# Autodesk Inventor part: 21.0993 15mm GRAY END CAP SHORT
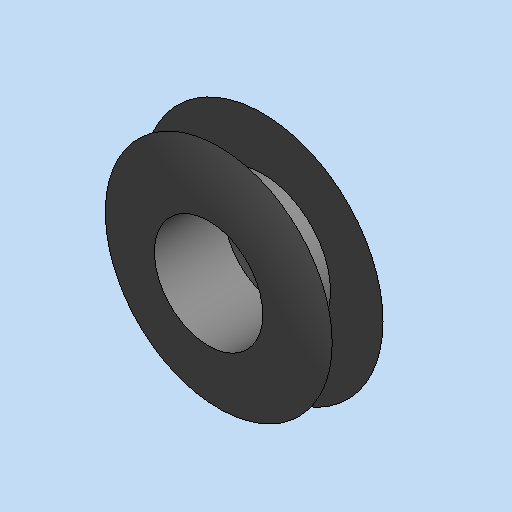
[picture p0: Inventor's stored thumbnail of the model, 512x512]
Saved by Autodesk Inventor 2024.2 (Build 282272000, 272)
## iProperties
Created: 2007-01
Part Number: 21.0993 15mm GRAY END CAP SHORT
Document SubType Name: Modeling
Designer: Andy Moles
Material: ABS Plastic
Density: 1.06 g/cm^3
Mass: 0.520799 g
Surface Area: 10.279 cm^2
Volume: 0.49132 cm^3
Appearance: Light Gray
Author: Andy Moles
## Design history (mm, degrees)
revolve "Revolution1" stored, may be unused: angle "d14" = 90 deg
body "Solid1"
sketch "Sketch1"
  geometry: L1 (8.875, -3)-(5, -3); L2 (5, -3)-(5, -5.79); L3 (4, -7)-(4, -1.841); L4 (0, -1.14)-(0, 0); A1 r 16.491 centre (-0.626, -16.479) between (8.875, -3) and (0, 0); A2 r 22.948 centre (3.594, -28.695) between (8.375, -6.25) and (5, -5.79); A3 r 21.456 centre (2.582, 14.409) between (4, -7) and (8.375, -6.25); A4 r 15.352 centre (-0.626, -16.479) between (4, -1.841) and (0, -1.14)
  constraints: 8 end point, 8 point on circle, 4 centre point, 2 parallel, 1 horizontal, 1 perpendicular
  dimensions: "d0" = 8.875 horizontal distance of L4.end L1.start; "d1" = 3 vertical distance of L1.start L4.end; "d15" = 0.5 horizontal distance of L1.start A2.start; "d23" = 7 vertical distance of L4.end L3.start; "d24" = 4 horizontal distance of L3.start L4.end; "d25" = 5 distance from line of L2 L4.end; "d26" = 1.21047 vertical distance of L3.start L2.end; "d27" = 8.375 horizontal distance of A2.start L4.end (derived); "d28" = 22.94823 radius of A2; "d29" = 21.45598 radius of A3; "d30" = 16.49124 radius of A1; "d31" = 3.25 distance from line of A2.start L1; "d32" = 15.35181 radius of A4
